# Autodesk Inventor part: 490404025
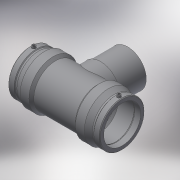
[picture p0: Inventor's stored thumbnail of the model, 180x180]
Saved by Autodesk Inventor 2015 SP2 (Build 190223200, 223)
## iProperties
Created: 2017-06
Part Number: 490404025
Material: Generic
Description: PLASSON TEE 25-25-25
Document SubType Name: Modeling
Designer: KIM
Mass: 113.577 g
Surface Area: 329.254 cm^2
Volume: 113.577 cm^3
Density: 1 g/cm^3
Appearance: Default
Author: KIM
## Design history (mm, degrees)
derived "490404.ipt"
feature "Solid1::490404.ipt"
tag "TaggingFeature1"
body "Solid1"
other parameters: "d0" = 103, "d1" = 25, "d2" = 44, "d3" = 39, "d4" = 25.75, "d5" = 39.6, "d6" = 23.75, "d7" = 25, "d8" = 168 deg, "d10" = 15.6, "d11" = 5.2, "d13" = 103, "d14" = 17.6296, "d17" = 22.5, "d18" = 25, "d19" = 3.52592, "d20" = 168 deg, "d22" = 40.92, "d23" = 44, "d24" = 39.6924, "d25" = 135 deg, "d26" = 72.1, "d27" = 135 deg, "d29" = 43, "d30" = 15, "d31" = 41.2, "d34" = 5 deg, "d35" = 15, "d39" = 5 deg, "d40" = 9.6, "d41" = 4.8, "d42" = 6, "d43" = 0, "d45" = 4, "d46" = 14, "d47" = 0, "d48" = -66, "d49" = 25, "d51" = 0, "d54" = 0, "d55" = 39.6, "d56" = 44, "d57" = 36.05, "d58" = 135 deg, "d59" = 39, "d60" = 39, "d61" = 135 deg, "d62" = 66, "d72" = 46.865, "d73" = 23.4325, "d74" = -66, "d75" = 26.25, "d77" = 0, "d80" = 0, "d81" = 25, "d82" = 44, "d83" = 0, "d84" = 3, "d85" = 0, "d86" = 3, "d87" = 0, "d88" = 11.31, "d89" = 2.8275, "d90" = 11.31, "d_" = 25, "L_" = 103, "L_1" = 39, "D_" = 44, "A_" = 43, "d_2" = 12, "H_" = 66
